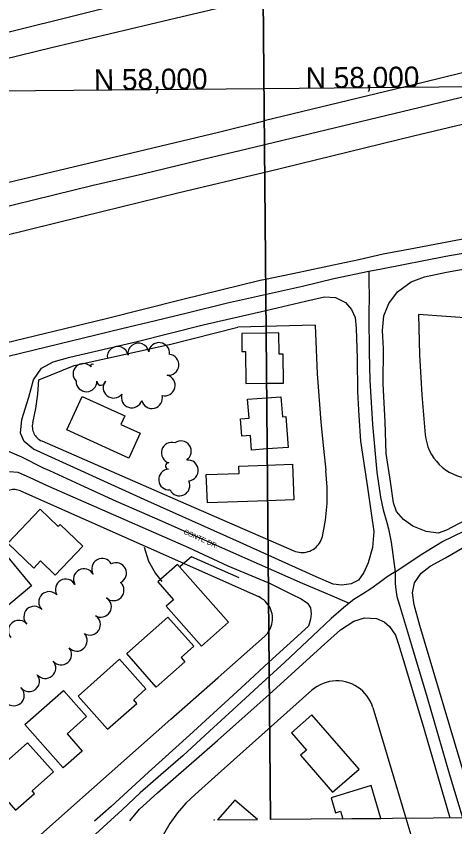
# Model space of a CAD drawing. Extents: x -2233 to 187241, y 4582 to 150524.
# Drawn here: x 109772 to 110191, y 57339 to 58113 of the extents above; entities that cross this region are included whole.
import ezdxf

# ---------------------------------------------------------------- set-up
doc = ezdxf.new("R2010")
doc.units = 0
for name, color, linetype in [('60', 7, 'Continuous'), ('BLDG', 7, 'Continuous'), ('GE_X_CL_2000', 7, 'Continuous'), ('GRID', 7, 'Continuous'), ('INTERSTATE', 7, 'Continuous'), ('ROAD', 7, 'Continuous'), ('ROAD-NAME', 7, 'Continuous'), ('RW_X_Fee_RW', 7, 'Continuous'), ('TREES', 7, 'Continuous'), ('WALL', 7, 'Continuous')]:
    doc.layers.add(name, color=color, linetype=linetype)

msp = doc.modelspace()

# ---------------------------------------------------------------- linework, layer by layer
at = {"layer": '60'}
for p, q in [((110014.63, 57345.92), (109991.08, 60043.59)), ((115014.43, 57389.55), (110014.63, 57345.92))]:
    msp.add_line(p, q, dxfattribs=at)
at = {"layer": 'BLDG'}
for p, q in [((110010.57, 57810.31), (109987.2, 57809.95)), ((110011.11, 57748.57), (110024.67, 57749.58)), ((110110.81, 57378.26), (110072.64, 57366.68)), ((110120.33, 57346.84), (110110.81, 57378.26)), ((109980.73, 57364.53), (109964.15, 57345.48)), ((110002.23, 57345.81), (109980.73, 57364.53)), ((110072.64, 57366.68), (110077, 57352.28)), ((110077, 57352.28), (110081.78, 57353.73)), ((110081.78, 57353.73), (110083.96, 57346.53)), ((110083.96, 57346.53), (110120.33, 57346.84)), ((109960.84, 57345.71), (109960.61, 57345.45)), ((109960.61, 57345.45), (109961.12, 57345.46)), ((109961.12, 57345.46), (109960.84, 57345.71)), ((109964.15, 57345.48), (110002.23, 57345.81))]:
    msp.add_line(p, q, dxfattribs=at)
for points in [[(110010.99, 57762.45), (110027.27, 57762.7), (110026.83, 57790.39), (110023, 57790.33), (110022.67, 57810.51), (110010.57, 57810.31)], [(109987.2, 57809.95), (109987.49, 57792.73), (109990.81, 57792.79), (109991.3, 57762.14), (110010.99, 57762.45)], [(110011.54, 57699.7), (109996.57, 57698.59), (109995.54, 57712.51), (109987.39, 57711.9), (109986.17, 57728.44), (109994.26, 57729.04), (109992.91, 57747.22), (110011.11, 57748.57)], [(110024.67, 57749.58), (110026.09, 57730.52), (110029.53, 57730.77), (110031.73, 57701.2), (110011.54, 57699.7)], [(109953.4, 57675.27), (109984.84, 57676.44), (109984.58, 57683.36), (110011.67, 57684.37)], [(110011.67, 57684.37), (110035.69, 57685.27), (110036.97, 57651.25), (110011.97, 57650.33)], [(110011.97, 57650.33), (109954.42, 57648.16), (109953.4, 57675.27)]]:
    msp.add_lwpolyline(points, dxfattribs=at)
for points in [[(109834.68, 57749.87), (109875.42, 57731.33), (109871.74, 57723.24), (109890.06, 57714.9), (109879.22, 57691.08), (109820.16, 57717.95)], [(109811.91, 57625.58), (109813.82, 57627.58), (109835.44, 57606.92), (109809.09, 57579.35), (109795.02, 57592.79), (109788.56, 57586.02), (109763.71, 57609.76), (109794.6, 57642.1)], [(109732.53, 57575.03), (109728.61, 57579.76), (109757.65, 57603.72), (109786.37, 57568.91), (109744.57, 57534.42), (109719.75, 57564.49)], [(109907.01, 57572.83), (109922.15, 57555.73), (109915.19, 57549.57), (109948.95, 57511.45), (109974.63, 57534.2), (109925.74, 57589.41)], [(109941.45, 57511.34), (109929.22, 57500.51), (109932.74, 57496.54), (109905.51, 57472.43), (109877.29, 57504.29), (109916.74, 57539.23)], [(109858.99, 57432.04), (109886.99, 57456.84), (109884, 57460.21), (109895.74, 57470.6), (109870.59, 57499), (109830.86, 57463.82)], [(109839, 57444.15), (109820.36, 57427.65), (109834.9, 57411.23), (109816.71, 57395.13), (109779.95, 57436.64), (109816.78, 57469.25)], [(110034.71, 57428.83), (110049.16, 57412.27), (110043.32, 57407.19), (110074.05, 57371.95), (110099.34, 57394.01), (110054.17, 57445.8)], [(109771.15, 57354.88), (109789.2, 57370.86), (109786.94, 57373.41), (109807.22, 57391.37), (109782.61, 57419.17), (109744.28, 57385.23)]]:
    msp.add_lwpolyline(points, close=True, dxfattribs=at)
at = {"layer": 'GE_X_CL_2000'}
for points in [[(109890.43, 58129.39), (109766.11, 58098.01), (109713.87, 58086.34), (109684.42, 58078.72), (109624.59, 58064.72), (109571.69, 58052.03), (109533.58, 58042.35), (109493.01, 58032.41), (109446.07, 58021.19), (109419.58, 58015.16), (109370.65, 58005.07), (109350.51, 58001.37), (109308.2, 57993.65), (109263.88, 57983.24), (109237.41, 57976.82), (109202.34, 57968.93), (109165.31, 57960.34), (109116.89, 57948.28), (109069.98, 57937.61)], [(109099.82, 57770.49), (109133.65, 57778.73), (109169.85, 57787.79), (109207.34, 57796.61), (109253.24, 57807.94), (109292.91, 57817.1), (109379.08, 57838.61), (109463.98, 57858.84), (109498.09, 57866.88), (109525.98, 57873.39), (109588.85, 57888.59), (109646.36, 57902.53), (109712.9, 57919.13), (109845.3, 57951.49), (109892.69, 57962.31), (109959.54, 57978.72), (109984.29, 57984.43), (110051.83, 58000.71), (110157.67, 58026.25), (110215.88, 58040.26)], [(110108.64, 57869.35), (110120.75, 57871.89), (110182.3, 57883.93), (110217.18, 57889.82), (110246.75, 57895.14), (110274.67, 57899.87), (110316.38, 57907.03), (110381.86, 57918.2), (110442.49, 57928.22), (110507.73, 57938.92), (110579.13, 57950.88), (110637.15, 57960.32), (110687.72, 57969.82), (110742.06, 57978.69), (110820.57, 57992.26), (110875.04, 58001.14), (110941.47, 58012.78), (110979.26, 58021.05), (110995.02, 58025.44), (111021.01, 58032.66)], [(109764.05, 57788.31), (109872.69, 57814.61), (109904.96, 57822.3), (109934.99, 57829.69), (109973.78, 57839.23), (110045.33, 57855.33), (110075.26, 57862.36), (110108.64, 57869.35)], [(110108.64, 57869.35), (110108.82, 57856.96), (110109.1, 57848.1), (110108.75, 57826.6), (110109.04, 57792.23), (110109.65, 57765.23), (110112.13, 57723.03), (110116.24, 57677.63), (110119.86, 57653.76), (110121.06, 57647.7), (110122.51, 57641.69), (110126.04, 57629.6), (110127.61, 57623.38), (110128.9, 57617.1), (110129.92, 57610.78), (110133.74, 57582.38)], [(110133.74, 57582.38), (110160.35, 57600.03), (110178.61, 57611.02), (110210.54, 57626.63), (110244.7, 57644.39), (110277.02, 57662.64), (110304.91, 57677.85), (110346.35, 57701.71), (110380.89, 57720.65), (110425.39, 57742.84), (110471.68, 57767.39), (110478.53, 57771.22)], [(109755.7, 57701.17), (109776.66, 57692.13), (109797.48, 57681.75), (109803.62, 57679.04), (109836.65, 57664.03), (109867.2, 57649.92), (109891.35, 57639.35), (109909.03, 57631.83), (109973.58, 57603.02), (110003.89, 57589.82), (110044.97, 57571.72), (110067.02, 57562.39), (110089.92, 57552.36)], [(110133.74, 57582.38), (110126.32, 57577.49), (110118.55, 57571.79), (110110.64, 57566.3), (110102.59, 57561), (110094.41, 57555.9), (110089.92, 57552.36)], [(110133.74, 57582.38), (110133.9, 57571.96), (110134.23, 57567.61), (110134.8, 57563.28), (110135.61, 57559), (110136.68, 57554.76), (110137.98, 57550.6), (110149.58, 57512.25), (110164.59, 57462.46), (110185.54, 57389.8), (110199.74, 57342.55)], [(110089.92, 57552.36), (110084.37, 57548), (110072.69, 57537.82), (110060.64, 57526.5), (110028.58, 57496.03), (110002.98, 57472.95), (109978.77, 57450.54), (109956.44, 57430.28), (109930.83, 57406.74), (109909.81, 57388.65), (109890.06, 57371.35), (109872.98, 57355.27), (109847.61, 57331.81)]]:
    msp.add_lwpolyline(points, dxfattribs=at)
at = {"layer": 'GRID'}
for p, q in [((109991.08, 60043.59), (110014.63, 57345.92)), ((109991.08, 60043.59), (110014.63, 57345.92)), ((115008.35, 58087.3), (110008.54, 58043.67)), ((110008.54, 58043.67), (105008.73, 58000.04))]:
    msp.add_line(p, q, dxfattribs=at)
at = {"layer": 'INTERSTATE'}
for points in [[(107597.52, 57549.5), (107639.58, 57559.64), (108082.57, 57666.27), (108479.64, 57762.05), (108633.94, 57800.03), (108810.66, 57842.91), (108925.35, 57870.8), (109005.25, 57889.5), (109049.55, 57900.16), (109099.56, 57911.91), (109173.05, 57930.02), (109251.22, 57949.31), (109334.21, 57969.06), (109422.55, 57990.57), (109525.47, 58015.09), (109651.47, 58045.45), (109805.57, 58083.08), (109918.32, 58109.9), (109996.57, 58128.54), (110007.77, 58131.27)], [(110492.35, 58129.97), (110326.51, 58090.37), (110160.77, 58049.76), (110008.8, 58012.95)], [(110009.23, 57963.89), (110012.3, 57964.62), (110151.35, 57998.85), (110299.92, 58034.2), (110469.77, 58075.42), (110491.92, 58080.72)], [(107604.86, 57431.69), (108480.8, 57643.54), (108556.79, 57661.73), (108652.2, 57685.55), (108719.19, 57701.21), (108806.62, 57722.59), (108991.06, 57767.15), (109122.27, 57798.94), (109296.81, 57841), (109414.34, 57870.16), (109597.88, 57914.58), (109799.41, 57962.78), (109965.07, 58002.36), (110008.8, 58012.95)], [(107610.7, 57363.77), (107659.85, 57377.23), (108015.73, 57473.08), (108255.59, 57536.11), (108436.62, 57583), (108481.29, 57593.91), (108601.06, 57623.56), (108709.58, 57649.58), (108811.98, 57674.17), (108935.48, 57704.49), (109067.52, 57736.34), (109179.9, 57763.55), (109308.66, 57794.45), (109409.22, 57818.81), (109506.68, 57842.8), (109597.89, 57864.48), (109679.73, 57884.32), (109757.97, 57903.08), (109835.31, 57922.11), (109926.34, 57944.24), (110009.23, 57963.89)]]:
    msp.add_lwpolyline(points, dxfattribs=at)
at = {"layer": 'ROAD'}
for p, q in [((109950.35, 57818.16), (110010.38, 57832.08)), ((110002.16, 57454.99), (110013.58, 57465.37))]:
    msp.add_line(p, q, dxfattribs=at)
for points in [[(110490.75, 57948.05), (110387.95, 57931.13), (110321.14, 57920.59), (110244.5, 57907.9), (110193.35, 57899.11), (110151.58, 57891.06), (110122.35, 57885.73), (110099.08, 57880.34), (110074.85, 57875.16), (110042.2, 57868.26), (110010.12, 57861.61)], [(110236.91, 57650.65), (110182.97, 57622.05), (110175.06, 57619.23), (110163.52, 57620.81), (110150.74, 57626.05), (110141.87, 57632.34), (110135.07, 57640.04), (110132.25, 57648.15), (110129.48, 57668.76), (110125.41, 57695.49), (110124.2, 57725.71), (110122.45, 57761.78), (110122.6, 57795.66), (110121.66, 57812.86), (110123.06, 57826.76), (110127.72, 57838.59), (110136.09, 57849.75), (110149.07, 57859.45), (110162.01, 57864.09), (110182.83, 57868.66), (110232.75, 57877.6)], [(110010.12, 57861.61), (110004.73, 57860.49), (109929.83, 57842.08), (109857.57, 57824.02), (109721.67, 57791.25), (109538.19, 57746.49), (109381.65, 57709.22), (109235.91, 57673.57), (108976.83, 57611.18), (108840.8, 57578.66), (108705.61, 57545.94), (108620.3, 57525.12), (108570.99, 57513.48), (108546.36, 57507.14), (108522.88, 57500.1), (108504.69, 57494.73), (108492.53, 57490.47), (108482.35, 57485.96)], [(110010.38, 57832.08), (110048.06, 57840.82), (110066.38, 57844.89), (110077.02, 57844.29), (110086.28, 57839.52), (110092, 57832.87), (110095.53, 57825.39), (110096.66, 57815.18), (110097.45, 57786.25), (110097.94, 57754.23), (110099.09, 57731.44), (110100.81, 57707.17), (110107.29, 57662.92), (110110.94, 57638.57), (110113.42, 57620.91), (110112.13, 57605.78), (110107.97, 57591.12), (110103.85, 57581.92), (110098.96, 57574.45), (110091.75, 57570.99), (110082.96, 57569.52), (110074.69, 57570.69), (110058.51, 57577.69), (110012.42, 57598.48)], [(110012.42, 57598.48), (109985.15, 57610.78), (109897.59, 57649.96), (109788.37, 57699.52), (109779.4, 57706.97), (109775.74, 57714.9), (109777.13, 57727.78), (109783.8, 57749.21), (109788.17, 57765.79), (109795.97, 57776.76), (109807.11, 57782.88), (109823, 57787.3), (109887.41, 57802.4), (109950.35, 57818.16)], [(110212.18, 57347.65), (110190.55, 57419.96), (110157.56, 57531.04), (110152.01, 57550.84), (110150.51, 57562.47), (110152.33, 57571.95), (110158.75, 57581), (110167.28, 57587.92), (110181.98, 57595.88), (110213.76, 57614.22), (110248.37, 57632.85), (110287.96, 57655.21), (110319.53, 57672.78), (110347.06, 57687.56), (110404.34, 57716.19), (110436.82, 57734.08), (110454.86, 57742.45), (110465.57, 57742.36), (110474.71, 57739.01), (110480.71, 57733.96), (110484.42, 57725.52), (110488.46, 57714.87)], [(109765.29, 57678.15), (109773.17, 57677.45), (109783.97, 57672.87), (109802.7, 57664.3), (109936.29, 57605.61), (109974.05, 57588.29), (110012.28, 57572.32), (110012.65, 57572.13)], [(110012.65, 57572.13), (110034.77, 57561.21), (110043.96, 57556.51), (110049.96, 57552.35), (110053.06, 57547.9), (110053.72, 57542.39), (110053.1, 57537.06), (110051.12, 57530.6), (110030.24, 57511.72), (110013.31, 57496.2)], [(110013.58, 57465.37), (110063.07, 57510.36), (110081.69, 57526.94), (110094.27, 57535.43), (110104.63, 57538.55), (110116.04, 57537.87), (110123.26, 57534.54), (110128.62, 57530.32), (110134.31, 57521.87), (110137.07, 57513.37), (110143.81, 57491.44), (110161.46, 57432.01), (110186.27, 57347.42)], [(110013.31, 57496.2), (109990.54, 57475.3), (109937.45, 57426.42), (109898.27, 57391.21), (109862.38, 57358.42), (109846.43, 57344.45)], [(109880.25, 57344.75), (109889.43, 57355.94), (109906.82, 57371.32), (109964.09, 57421.38), (110002.16, 57454.99)]]:
    msp.add_lwpolyline(points, dxfattribs=at)
at = {"layer": 'RW_X_Fee_RW'}
for p, q in [((110307.64, 57816.84), (110156.28, 57828.08)), ((110057.52, 57817.84), (109983.67, 57816.18)), ((109827.21, 57779.53), (109917.99, 57799.51)), ((109793.38, 57765.79), (109827.21, 57779.53))]:
    msp.add_line(p, q, dxfattribs=at)
for points in [[(110156.28, 57828.08), (110157.2, 57789.76), (110158.38, 57768.13), (110159.29, 57751.49), (110162.55, 57713.29)], [(109917.99, 57799.51), (109918.35, 57799.6), (109983.67, 57816.18)], [(110057.52, 57817.84), (110059.36, 57771.47), (110060.28, 57758.99), (110062.79, 57725.19), (110065.49, 57700.31), (110067.75, 57679.04)], [(109787.5, 57724.67), (109790.33, 57738.24), (109792.3, 57751.96), (109793.38, 57765.79)], [(109787.5, 57724.67), (109787.25, 57723.38), (109787.11, 57722.08), (109787.08, 57720.77), (109787.17, 57719.46), (109787.37, 57718.17), (109787.69, 57716.9), (109788.11, 57715.66), (109788.64, 57714.46), (109789.28, 57713.31), (109790.01, 57712.23), (109790.83, 57711.21), (109791.74, 57710.26), (109792.73, 57709.4), (109793.79, 57708.63), (109794.91, 57707.96), (109796.09, 57707.38)], [(110162.55, 57713.29), (110163.12, 57709.34), (110164.03, 57705.46), (110165.26, 57701.66), (110166.81, 57697.99), (110168.68, 57694.46), (110170.83, 57691.1), (110173.27, 57687.94), (110175.97, 57685), (110178.91, 57682.3), (110182.07, 57679.86), (110185.42, 57677.7), (110188.95, 57675.83), (110192.63, 57674.28), (110196.42, 57673.04), (110200.31, 57672.13), (110204.26, 57671.56), (110208.24, 57671.33), (110212.23, 57671.44), (110216.2, 57671.89), (110220.11, 57672.67), (110223.94, 57673.79), (110227.66, 57675.23), (110231.25, 57676.99)], [(109796.09, 57707.38), (109928.71, 57649.64), (110036.96, 57602.51)], [(110064.42, 57616.28), (110067.33, 57631.79), (110068.86, 57647.51), (110068.98, 57663.3), (110067.75, 57679.04)], [(109775.76, 57659.69), (109774.54, 57660.17), (109773.28, 57660.54), (109772, 57660.8), (109770.7, 57660.95), (109769.39, 57660.98), (109768.08, 57660.9), (109766.79, 57660.71), (109765.51, 57660.4), (109764.27, 57659.98), (109763.07, 57659.46), (109761.92, 57658.83), (109760.83, 57658.1), (109759.81, 57657.29), (109758.86, 57656.38), (109757.99, 57655.4), (109757.21, 57654.34)], [(109775.76, 57659.69), (109894.94, 57606.76), (110003.14, 57558.7)], [(110036.96, 57602.51), (110038.59, 57601.88), (110040.28, 57601.4), (110041.99, 57601.06), (110043.74, 57600.88), (110045.49, 57600.85), (110047.23, 57600.98), (110048.96, 57601.25), (110050.66, 57601.68), (110052.31, 57602.25), (110053.91, 57602.97), (110055.44, 57603.82), (110056.89, 57604.8), (110058.24, 57605.91), (110059.5, 57607.13), (110060.64, 57608.45), (110061.67, 57609.87), (110062.56, 57611.38), (110063.32, 57612.95), (110063.94, 57614.59), (110064.42, 57616.28)], [(110009, 57520.66), (110010.44, 57522.04), (110011.74, 57523.54), (110012.91, 57525.15), (110013.94, 57526.85), (110014.81, 57528.63), (110015.53, 57530.49), (110016.08, 57532.4), (110016.47, 57534.35), (110016.68, 57536.32), (110016.72, 57538.31), (110016.59, 57540.29), (110016.29, 57542.26), (110015.82, 57544.19), (110015.18, 57546.07), (110014.38, 57547.89), (110013.43, 57549.64), (110012.32, 57551.29), (110011.08, 57552.84), (110009.71, 57554.28), (110008.22, 57555.6), (110006.62, 57556.77), (110004.92, 57557.81), (110003.14, 57558.7)], [(109783.91, 57321.71), (109786.26, 57323.79), (109829.72, 57362.2), (109874.68, 57401.94), (109919.64, 57441.67), (109964.59, 57481.41), (110009, 57520.66)], [(110112.59, 57452.71), (110111.56, 57455.66), (110110.28, 57458.52), (110108.76, 57461.25), (110107.01, 57463.84), (110105.03, 57466.27), (110102.86, 57468.52), (110100.49, 57470.57), (110097.96, 57472.4), (110095.27, 57474.01), (110092.46, 57475.37), (110089.53, 57476.49), (110086.52, 57477.34), (110083.45, 57477.94), (110080.34, 57478.26), (110077.21, 57478.3), (110074.09, 57478.08), (110071, 57477.58), (110067.97, 57476.82), (110065.01, 57475.8), (110062.15, 57474.52), (110059.42, 57473), (110056.83, 57471.24), (110054.4, 57469.27)], [(110054.4, 57469.27), (109964.69, 57389.56), (109942.59, 57369.92)], [(110112.59, 57452.71), (110132.59, 57385.63), (110144.03, 57347.3), (110146.88, 57337.71), (110155.46, 57308.96), (110161.17, 57289.8), (110166.89, 57270.63), (110175.46, 57241.88), (110178.32, 57232.3), (110189.75, 57193.97), (110201.19, 57155.64)], [(109942.59, 57369.92), (109933.8, 57361.4), (109925.79, 57352.14), (109918.62, 57342.21), (109912.34, 57331.7), (109907.01, 57320.68), (109905.53, 57316.76), (109902.66, 57309.23), (109899.33, 57297.45), (109897.04, 57285.42), (109895.82, 57273.24), (109895.66, 57260.99), (109896.57, 57248.78), (109897.49, 57243.16), (109898.55, 57236.7), (109901.57, 57224.83)]]:
    msp.add_lwpolyline(points, dxfattribs=at)
at = {"layer": 'TREES'}
for centre, radius, start, end in [((109868.72, 57787.6), 10, 9.33804, 189.33804), ((109888.45, 57790.84), 10, 9.33804, 189.33804), ((109908.25, 57791.27), 10, 353.13169, 173.13169), ((109917.15, 57780.12), 10, 264.09442, 84.09442), ((109836.08, 57771.29), 10, 44.12677, 224.12677), ((109844.36, 57779.32), 1.53, 44.12677, 224.12677), ((109838.9, 57764.41), 10, 180.48564, 0.48564), ((109852.93, 57764.53), 4.03, 180.48564, 0.48564), ((109864.8, 57758.36), 10, 141.65103, 321.65103), ((109913.6, 57760.5), 10, 255.43057, 75.43057), ((109882.16, 57749.08), 10, 162.07655, 342.07655), ((109901.38, 57748.41), 10, 193.95045, 13.95045), ((109920.49, 57696.07), 10, 73.54533, 253.54533), ((109929, 57697.42), 10, 304.54537, 124.54537), ((109935.68, 57679.24), 10, 275.83242, 95.83242), ((109917.91, 57670.54), 10, 94.57189, 274.57189), ((109917.39, 57683.49), 3, 84.70547, 264.70547), ((109927.7, 57664.93), 10, 205.85411, 25.85411), ((109853.91, 57585.17), 10, 29.47676, 209.47676), ((109867.08, 57581.14), 10, 296.4635, 116.4635), ((109836.5, 57575.33), 10, 29.47676, 209.47676), ((109819.11, 57565.46), 10, 29.66903, 209.66903), ((109864.71, 57564.87), 10, 227.01259, 47.01259), ((109803.28, 57553.5), 10, 44.44779, 224.44779), ((109852.65, 57549.04), 10, 238.39193, 58.39193), ((109789, 57539.5), 10, 44.4478, 224.4478), ((109842.15, 57532.02), 10, 238.2565, 58.2565), ((109774.19, 57526.09), 10, 39.87224, 219.87224), ((109829.59, 57516.68), 10, 223.13948, 43.13948), ((109814.72, 57503.45), 9.91, 220.14903, 40.14903), ((109799.5, 57490.61), 10, 220.14903, 40.14903), ((109783.95, 57478.05), 10, 217.70707, 37.70707), ((109769.44, 57464.42), 10, 228.71641, 48.71641)]:
    msp.add_arc(centre, radius, start, end, dxfattribs=at)
at = {"layer": 'WALL'}
for points in [[(109894, 57605.91), (109898.06, 57592.6), (109904.76, 57580.87), (109910.8, 57573.31)], [(109984.66, 57576.52), (109939.35, 57596.67), (109928.42, 57587.46)]]:
    msp.add_lwpolyline(points, dxfattribs=at)

# ---------------------------------------------------------------- texts
at = {"layer": 'GRID'}
for p in [(109846.09, 58042.25), (110048.53, 58044.02)]:
    msp.add_text('N 58,000', height=20, rotation=0.5, dxfattribs=at).set_placement(p)
at = {"layer": 'ROAD-NAME'}
msp.add_text('CONTE DR.', height=4.68, rotation=335.83355, dxfattribs=at).set_placement((109931.11, 57619.07))

doc.saveas('drawing.dxf')
